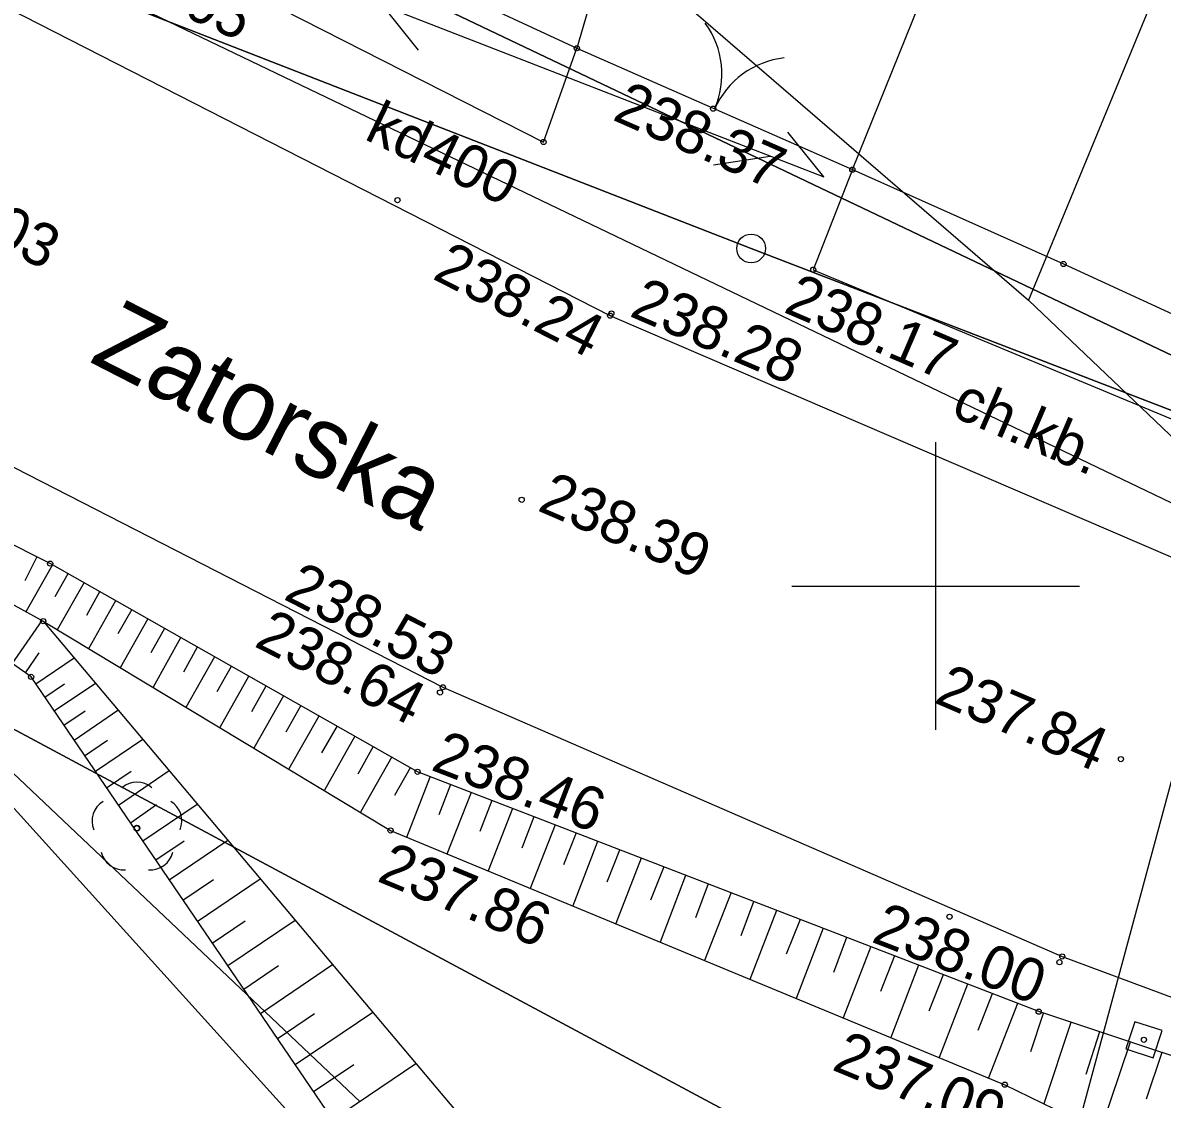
# Model space of a CAD drawing. Extents: x 6596400 to 6597200, y 5539751 to 5540251.
# Drawn here: x 6596684.12 to 6596703.94, y 5540092.08 to 5540110.79 of the extents above; entities that cross this region are included whole.
import ezdxf

# ---------------------------------------------------------------- set-up
doc = ezdxf.new("R2010")
doc.units = 0
for name, color, linetype in [('000 Inne (niezydentyfikowane)', 7, 'Continuous'), ('140-Punkty robocze', 7, 'Continuous'), ('202-punkt graniczny', 7, 'Continuous'), ('217-kontur klasyfikacyjny', 7, 'Continuous'), ('218-kontur użytku gruntowego', 7, 'Continuous'), ('219-działka ewidencyjna', 7, 'Continuous'), ('994-Nazwa ulicy', 7, 'Continuous'), ('brama', 7, 'Continuous'), ('chodnik', 7, 'Continuous'), ('chodnik-Atr17', 7, 'Continuous'), ('drzewo liściaste', 7, 'Continuous'), ('jezdnia', 7, 'Continuous'), ('krawężnik', 7, 'Continuous'), ('Linia obszaru zagospodarowania terenu', 7, 'Continuous'), ('ogrodzenie trwałe', 7, 'Continuous'), ('pikieta sztuczna', 7, 'Continuous'), ('pikieta sztuczna-Atr2', 7, 'Continuous'), ('przewód kanalizacyjny', 7, 'Continuous'), ('przewód kanalizacyjny-Atr1', 7, 'Continuous'), ('przewód telekomunikacyjny napowietrzny', 7, 'Continuous'), ('skarpa nieumocniona', 7, 'Continuous'), ('Strefa korytarza ekologicznego', 7, 'Continuous'), ('Wstawianie ramki sekcyjnej z opisem', 7, 'Continuous'), ('właz do komory lub kanału - kwadratowy', 7, 'Continuous')]:
    doc.layers.add(name, color=color, linetype=linetype)

# ---------------------------------------------------------------- blocks, each defined once
blk = doc.blocks.new('202')
blk.add_circle((0, 0), 0.25)
blk = doc.blocks.new('SUTP')
for p, q in [((0, 0), (0.866, 0.5)), ((9.232, 0), (8.366, 0.5)), ((0, 0), (9.232, 0)), ((1.866, -0.5), (1, 0)), ((7.366, -0.5), (8.232, 0))]:
    blk.add_line(p, q)
blk = doc.blocks.new('OK02')
for centre, start, end in [((-1.5, 0), 0, 60), ((1.5, 0), 120, 180)]:
    blk.add_arc(centre, 1.5, start, end)
blk = doc.blocks.new('OP021')
blk.add_circle((0, 0), 0.05)
for centre, start, end in [((0, 0.4), 49.272, 130.728), ((-0.38, 0.124), 121.308, 202.548), ((0.38, 0.124), 337.452, 58.692), ((-0.235, -0.324), 193.221, 274.871), ((0.235, -0.324), 265.129, 346.779)]:
    blk.add_arc(centre, 0.4, start, end)
blk = doc.blocks.new('US22A')
blk.add_lwpolyline([(-0.25, -0.25), (0.25, -0.25), (0.25, 0.25), (-0.25, 0.25)], close=True)
blk = doc.blocks.new('RAMKA500K')
for p, q in [((300, 98.5), (300, 103.5)), ((297.5, 101), (302.5, 101))]:
    blk.add_line(p, q)
blk = doc.blocks.new('PIKIETA')
blk.add_circle((0, 0), 0.045)
blk = doc.blocks.new('PW01')
blk.add_circle((0, 0), 0.045)

msp = doc.modelspace()

# ---------------------------------------------------------------- linework, layer by layer
at = {"layer": '000 Inne (niezydentyfikowane)'}
for p, q in [((6596683.94, 5540099.65), (6596684.46, 5540100.4)), ((6596684.17, 5540099.49), (6596684.41, 5540099.84)), ((6596684.35, 5540099.3), (6596685.02, 5540099.75)), ((6596684.51, 5540099.07), (6596684.85, 5540099.3)), ((6596684.67, 5540098.83), (6596685.39, 5540099.31)), ((6596684.84, 5540098.58), (6596685.21, 5540098.83)), ((6596685.02, 5540098.32), (6596685.78, 5540098.84)), ((6596685.2, 5540098.05), (6596685.6, 5540098.32)), ((6596685.39, 5540097.78), (6596686.21, 5540098.34)), ((6596685.58, 5540097.49), (6596686.01, 5540097.78)), ((6596685.79, 5540097.19), (6596686.67, 5540097.79)), ((6596686, 5540096.88), (6596686.45, 5540097.2)), ((6596686.21, 5540096.57), (6596687.16, 5540097.21)), ((6596686.44, 5540096.24), (6596686.93, 5540096.57)), ((6596686.67, 5540095.89), (6596687.69, 5540096.58)), ((6596686.91, 5540095.54), (6596687.44, 5540095.9)), ((6596687.16, 5540095.17), (6596688.25, 5540095.91)), ((6596687.42, 5540094.79), (6596687.99, 5540095.18)), ((6596687.69, 5540094.4), (6596688.86, 5540095.19)), ((6596687.97, 5540093.99), (6596688.57, 5540094.4)), ((6596688.26, 5540093.57), (6596689.51, 5540094.42)), ((6596688.55, 5540093.13), (6596689.2, 5540093.57)), ((6596688.86, 5540092.68), (6596690.21, 5540093.59)), ((6596689.18, 5540092.21), (6596689.88, 5540092.68)), ((6596689.51, 5540091.72), (6596690.96, 5540092.7))]:
    msp.add_line(p, q, dxfattribs=at)
for points in [[(6596684.37, 5540101.51), (6596684.16, 5540101.09)], [(6596684.64, 5540101.37), (6596684.18, 5540100.55)], [(6596684.91, 5540101.21), (6596684.68, 5540100.81)], [(6596685.19, 5540101.06), (6596684.72, 5540100.24)], [(6596685.46, 5540100.9), (6596685.23, 5540100.49)], [(6596685.74, 5540100.74), (6596685.27, 5540099.91)], [(6596686.02, 5540100.59), (6596685.78, 5540100.17)], [(6596686.3, 5540100.43), (6596685.82, 5540099.58)], [(6596686.59, 5540100.26), (6596686.35, 5540099.84)], [(6596686.87, 5540100.1), (6596686.39, 5540099.24)], [(6596687.16, 5540099.94), (6596686.92, 5540099.5)], [(6596687.46, 5540099.77), (6596686.96, 5540098.89)], [(6596687.75, 5540099.6), (6596687.5, 5540099.16)], [(6596688.05, 5540099.43), (6596687.55, 5540098.54)], [(6596688.35, 5540099.26), (6596688.1, 5540098.81)], [(6596688.66, 5540099.09), (6596688.14, 5540098.18)], [(6596688.96, 5540098.92), (6596688.7, 5540098.46)], [(6596689.27, 5540098.74), (6596688.75, 5540097.82)], [(6596689.59, 5540098.57), (6596689.32, 5540098.1)], [(6596689.9, 5540098.39), (6596689.37, 5540097.45)], [(6596690.22, 5540098.21), (6596689.95, 5540097.73)], [(6596690.54, 5540098.03), (6596690, 5540097.07)], [(6596690.86, 5540097.84), (6596690.59, 5540097.36)], [(6596691.21, 5540097.69), (6596690.8, 5540096.63)], [(6596691.56, 5540097.55), (6596691.36, 5540097.02)], [(6596691.92, 5540097.41), (6596691.5, 5540096.34)], [(6596692.28, 5540097.27), (6596692.07, 5540096.73)], [(6596692.64, 5540097.13), (6596692.22, 5540096.05)], [(6596693.01, 5540096.99), (6596692.8, 5540096.44)], [(6596693.38, 5540096.85), (6596692.95, 5540095.74)], [(6596693.75, 5540096.71), (6596693.53, 5540096.15)], [(6596694.12, 5540096.56), (6596693.69, 5540095.44)], [(6596694.5, 5540096.41), (6596694.28, 5540095.85)], [(6596694.88, 5540096.27), (6596694.44, 5540095.13)], [(6596695.27, 5540096.12), (6596695.04, 5540095.54)], [(6596695.65, 5540095.97), (6596695.21, 5540094.81)], [(6596696.04, 5540095.82), (6596695.82, 5540095.23)], [(6596696.44, 5540095.67), (6596695.98, 5540094.49)], [(6596696.83, 5540095.51), (6596696.61, 5540094.92)], [(6596697.23, 5540095.36), (6596696.77, 5540094.16)], [(6596697.64, 5540095.2), (6596697.4, 5540094.6)], [(6596698.04, 5540095.05), (6596697.57, 5540093.83)], [(6596698.45, 5540094.89), (6596698.22, 5540094.28)], [(6596698.87, 5540094.73), (6596698.39, 5540093.49)], [(6596699.28, 5540094.57), (6596699.04, 5540093.95)], [(6596699.7, 5540094.41), (6596699.22, 5540093.15)], [(6596700.13, 5540094.24), (6596699.88, 5540093.61)], [(6596700.55, 5540094.08), (6596700.06, 5540092.8)], [(6596700.98, 5540093.91), (6596700.73, 5540093.27)], [(6596701.42, 5540093.74), (6596700.92, 5540092.45)], [(6596701.87, 5540093.57), (6596701.65, 5540092.9)], [(6596702.35, 5540093.41), (6596701.88, 5540092)], [(6596702.85, 5540093.25), (6596702.61, 5540092.51)], [(6596703.38, 5540093.07), (6596702.86, 5540091.52)], [(6596703.93, 5540092.89), (6596703.66, 5540092.08)]]:
    msp.add_lwpolyline(points, dxfattribs=at)
at = {"layer": '217-kontur klasyfikacyjny'}
msp.add_lwpolyline([(6596689.99, 5540092.03), (6596682.08, 5540099.52)], dxfattribs=at)
at = {"layer": '218-kontur użytku gruntowego'}
for points in [[(6596714.65, 5540099.99), (6596686.48, 5540113.41)], [(6596686.48, 5540113.41), (6596714.65, 5540099.99)], [(6596685.7, 5540111.19), (6596696.79, 5540106.87)], [(6596696.79, 5540106.87), (6596685.7, 5540111.19)], [(6596696.79, 5540106.87), (6596714.65, 5540099.99)], [(6596714.65, 5540099.99), (6596696.79, 5540106.87)], [(6596689.99, 5540092.03), (6596682.08, 5540099.52)], [(6596682.08, 5540099.52), (6596689.99, 5540092.03)], [(6596712.64, 5540083.14), (6596682.08, 5540099.52)], [(6596682.08, 5540099.52), (6596712.64, 5540083.14)]]:
    msp.add_lwpolyline(points, dxfattribs=at)
at = {"layer": '219-działka ewidencyjna'}
for points in [[(6596696.79, 5540106.87), (6596685.7, 5540111.19)], [(6596714.65, 5540099.99), (6596696.79, 5540106.87)], [(6596712.64, 5540083.14), (6596682.08, 5540099.52)], [(6596689.99, 5540092.03), (6596682.08, 5540099.52)]]:
    msp.add_lwpolyline(points, dxfattribs=at)
at = {"layer": 'brama'}
msp.add_lwpolyline([(6596693.76, 5540110.35), (6596698.55, 5540108.24)], dxfattribs=at)
at = {"layer": 'chodnik'}
for points in [[(6596672.08, 5540122.71), (6596677.31, 5540119.95), (6596676.14, 5540117.82), (6596682.08, 5540114.47), (6596682.62, 5540115.47), (6596686.44, 5540113.75), (6596685.85, 5540112.45), (6596693.18, 5540108.72), (6596693.76, 5540110.35), (6596698.55, 5540108.24), (6596697.87, 5540106.5), (6596705.5, 5540103.32), (6596709.65, 5540101.73), (6596713.73, 5540100.03), (6596712.8, 5540098.2), (6596708.8, 5540099.55), (6596704.7, 5540101.24), (6596694.34, 5540105.7), (6596683.34, 5540111.32), (6596679.35, 5540113.39), (6596672.62, 5540117.3)], [(6596696.877, 5540121.033), (6596693.76, 5540110.35), (6596698.55, 5540108.24), (6596703.628, 5540120.812)]]:
    msp.add_lwpolyline(points, dxfattribs=at)
at = {"layer": 'jezdnia'}
for points in [[(6596728.26, 5540094.5), (6596723.35, 5540095.14), (6596720.92, 5540095.72), (6596718.03, 5540096.54), (6596712.8, 5540098.2), (6596708.8, 5540099.55), (6596704.7, 5540101.24), (6596694.34, 5540105.7), (6596683.34, 5540111.32), (6596679.35, 5540113.39), (6596672.62, 5540117.3), (6596666.82, 5540120.65), (6596657.79, 5540125.88), (6596655.967, 5540126.802)], [(6596653.124, 5540120.82), (6596653.79, 5540120.41), (6596660.56, 5540116.72), (6596663.8, 5540114.85), (6596668, 5540112.34), (6596669.54, 5540111.42), (6596675.97, 5540107.49), (6596679.93, 5540105.19), (6596682.35, 5540103.89), (6596691.43, 5540099.24), (6596702.2, 5540094.56), (6596706.34, 5540093.02), (6596710.59, 5540091.59), (6596715.92, 5540090.16), (6596720.02, 5540089.23), (6596724.29, 5540088.47), (6596726.93, 5540087.96), (6596734.57, 5540086.51), (6596738.41, 5540085.75), (6596741.83, 5540085.11), (6596743.38, 5540084.84), (6596743.64, 5540085.7), (6596748.72, 5540084.9)]]:
    msp.add_lwpolyline(points, dxfattribs=at)
at = {"layer": 'krawężnik'}
for points in [[(6596712.8, 5540098.2), (6596708.8, 5540099.55), (6596704.7, 5540101.24), (6596694.34, 5540105.7), (6596683.34, 5540111.32), (6596679.35, 5540113.39), (6596672.62, 5540117.3), (6596666.82, 5540120.65), (6596657.79, 5540125.88), (6596655.967, 5540126.802)], [(6596653.124, 5540120.82), (6596653.79, 5540120.41), (6596660.56, 5540116.72), (6596663.8, 5540114.85), (6596668, 5540112.34), (6596669.54, 5540111.42), (6596675.97, 5540107.49), (6596679.93, 5540105.19), (6596682.35, 5540103.89), (6596691.43, 5540099.24), (6596702.2, 5540094.56), (6596706.34, 5540093.02), (6596710.59, 5540091.59)]]:
    msp.add_lwpolyline(points, dxfattribs=at)
at = {"layer": 'Linia obszaru zagospodarowania terenu'}
for points in [[(6596664.616, 5540132.112), (6596671.21, 5540127.95), (6596681.8, 5540121.54), (6596690.35, 5540115.69), (6596701.61, 5540105.97), (6596709.34, 5540098.61), (6596715.39, 5540091.82), (6596718.63, 5540088.53), (6596721.87, 5540084.71), (6596726.1, 5540083.21), (6596730.7, 5540082.79), (6596730.91, 5540075), (6596745.51, 5540074.64), (6596746.77, 5540082.74), (6596765.15, 5540085.09), (6596776.62, 5540086.27), (6596789.34, 5540086.1), (6596798.37, 5540085.54), (6596805.65, 5540083.56), (6596813.11, 5540081.53), (6596819.41, 5540077.54), (6596826.58, 5540072.81), (6596832.721, 5540067.998)], [(6596706.97, 5540120.853), (6596706.57, 5540117.98), (6596701.61, 5540105.97)]]:
    msp.add_lwpolyline(points, dxfattribs=at)
at = {"layer": 'ogrodzenie trwałe'}
for points in [[(6596686.44, 5540113.75), (6596693.76, 5540110.35)], [(6596667.03, 5540110.64), (6596668.29, 5540109.72), (6596674.46, 5540105.01), (6596681.86, 5540099.47), (6596691.51, 5540088.79), (6596685.94, 5540084.598)], [(6596698.55, 5540108.24), (6596702.22, 5540106.6), (6596706.01, 5540104.86), (6596709.96, 5540103.02), (6596712.81, 5540101.64), (6596714.61, 5540101.89)]]:
    msp.add_lwpolyline(points, dxfattribs=at)
at = {"layer": 'przewód kanalizacyjny'}
msp.add_lwpolyline([(6596652.409, 5540119.314), (6596659.51, 5540115.47), (6596667.73, 5540121.28), (6596680.3, 5540113.87), (6596707.99, 5540100.58), (6596711.34, 5540100.47), (6596715.95, 5540100.45)], dxfattribs=at)
at = {"layer": 'skarpa nieumocniona'}
for points in [[(6596678.95, 5540103.44), (6596684.48, 5540100.39), (6596690.52, 5540096.75), (6596701.2, 5540092.33), (6596705.49, 5540090.24), (6596709.93, 5540088.59), (6596713.91, 5540088.19), (6596713.79, 5540089.29), (6596710.4, 5540090.34), (6596706.06, 5540092.18), (6596701.79, 5540093.6), (6596690.99, 5540097.77), (6596684.6, 5540101.39), (6596679.33, 5540104.04), (6596675.06, 5540106.16)], [(6596678.95, 5540103.44), (6596684.48, 5540100.39), (6596690.52, 5540096.75), (6596701.2, 5540092.33), (6596705.49, 5540090.24), (6596709.93, 5540088.59), (6596713.91, 5540088.19), (6596713.79, 5540089.29), (6596710.4, 5540090.34), (6596706.06, 5540092.18), (6596701.79, 5540093.6), (6596690.99, 5540097.77), (6596684.6, 5540101.39), (6596679.33, 5540104.04), (6596675.06, 5540106.16)], [(6596678.95, 5540103.44), (6596684.48, 5540100.39), (6596694.1, 5540088.97), (6596698.32, 5540084.27), (6596700.74, 5540077.75), (6596705.03, 5540070.97), (6596697.73, 5540077), (6596697.69, 5540077.02), (6596691.51, 5540088.79), (6596684.27, 5540099.42), (6596679.14, 5540103.03), (6596675.06, 5540106.16)], [(6596678.95, 5540103.44), (6596684.48, 5540100.39), (6596694.1, 5540088.97), (6596698.32, 5540084.27), (6596700.74, 5540077.75), (6596705.03, 5540070.97), (6596697.73, 5540077), (6596697.69, 5540077.02), (6596691.51, 5540088.79), (6596684.27, 5540099.42), (6596679.14, 5540103.03), (6596675.06, 5540106.16)]]:
    msp.add_lwpolyline(points, close=True, dxfattribs=at)
at = {"layer": 'Strefa korytarza ekologicznego'}
msp.add_lwpolyline([(6596698.383, 5540076.46), (6596706.03, 5540104.75), (6596710.01, 5540120.89)], dxfattribs=at)

# ---------------------------------------------------------------- block references
at = {"layer": '140-Punkty robocze'}
for p in [(6596693.76, 5540110.35), (6596693.18, 5540108.72), (6596698.55, 5540108.24), (6596690.64, 5540107.71), (6596702.22, 5540106.6), (6596684.6, 5540101.39), (6596684.48, 5540100.39), (6596684.27, 5540099.42), (6596686.11, 5540096.79), (6596700.24, 5540095.25), (6596702.15, 5540094.46), (6596702.2, 5540094.56), (6596703.62, 5540093.11)]:
    msp.add_blockref('PIKIETA', p, dxfattribs=at)
at = {"layer": '202-punkt graniczny'}
msp.add_blockref('202', (6596696.79, 5540106.87), dxfattribs=at)
at = {"layer": 'brama', "rotation": -23.774}
msp.add_blockref('OK02', (6596696.155, 5540109.295), dxfattribs=at)
at = {"layer": 'drzewo liściaste'}
msp.add_blockref('OP021', (6596686.11, 5540096.79), dxfattribs=at)
at = {"layer": 'pikieta sztuczna'}
for p in [(6596696.13, 5540109.3), (6596697.87, 5540106.5), (6596694.36, 5540105.74), (6596694.34, 5540105.7), (6596692.8, 5540102.5), (6596691.43, 5540099.24), (6596691.38, 5540099.15), (6596703.22, 5540097.99), (6596690.99, 5540097.77), (6596690.52, 5540096.75), (6596701.79, 5540093.6), (6596701.2, 5540092.33)]:
    msp.add_blockref('PW01', p, dxfattribs=at)
at = {"layer": 'przewód telekomunikacyjny napowietrzny', "rotation": -21.254999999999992}
msp.add_blockref('SUTP', (6596689.45, 5540111.46), dxfattribs=at)
at = {"layer": 'Wstawianie ramki sekcyjnej z opisem'}
msp.add_blockref('RAMKA500K', (6596400, 5540000), dxfattribs=at)
at = {"layer": 'właz do komory lub kanału - kwadratowy', "rotation": -18.19900000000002}
msp.add_blockref('US22A', (6596703.62, 5540093.11), dxfattribs=at)

# ---------------------------------------------------------------- texts
at = {"layer": '994-Nazwa ulicy'}
msp.add_text('Zatorska', height=1.25, rotation=332.882, dxfattribs=at).set_placement((6596685.26, 5540104.91))
at = {"layer": 'chodnik-Atr17'}
msp.add_text('ch.kb.', height=0.75, rotation=336.708, dxfattribs=at).set_placement((6596700.24, 5540103.97))
at = {"layer": 'pikieta sztuczna-Atr2'}
for s, rotation, p in [('239.05', 335.76, (6596685.102, 5540111.726)), ('238.37', 336.226, (6596694.358, 5540109.114)), ('239.03', 332.937, (6596681.779, 5540107.882)), ('238.24', 332.937, (6596691.229, 5540106.352)), ('238.17', 336.708, (6596697.333, 5540105.771)), ('238.28', 336.708, (6596694.653, 5540105.701)), ('238.39', 336.708, (6596693.053, 5540102.321)), ('238.53', 332.882, (6596688.638, 5540100.782)), ('238.64', 332.882, (6596688.128, 5540099.962)), ('237.84', 336.708, (6596699.953, 5540098.981)), ('238.46', 338.888, (6596691.2, 5540097.81)), ('237.86', 337.517, (6596690.263, 5540095.877)), ('238.00', 338.888, (6596698.86, 5540094.82)), ('237.09', 337.517, (6596698.173, 5540092.597))]:
    msp.add_text(s, height=0.75, rotation=rotation, dxfattribs=at).set_placement(p)
at = {"layer": 'przewód kanalizacyjny-Atr1'}
msp.add_text('kd400', height=0.75, rotation=334.361, dxfattribs=at).set_placement((6596690.042, 5540108.779))

doc.saveas('drawing.dxf')
